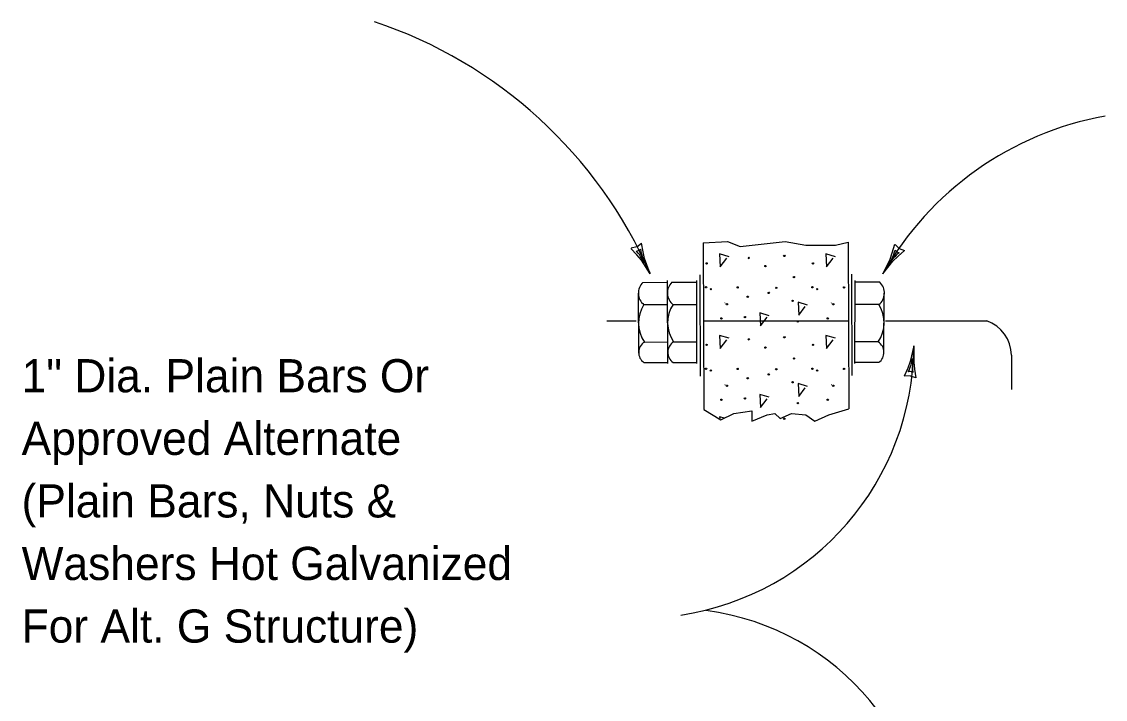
# Model space of a CAD drawing. Extents: x -7.1 to 10, y -5 to 6.
# Drawn here: x 4.345 to 6.081, y 3.626 to 4.713 of the extents above; entities that cross this region are included whole.
import ezdxf

# ---------------------------------------------------------------- set-up
doc = ezdxf.new("R2010")
doc.units = 0
for name, color, linetype in [('Level 4', 7, 'Continuous'), ('Level 5', 7, 'Continuous'), ('Level 6', 7, 'Continuous'), ('Level 7', 7, 'Continuous')]:
    doc.layers.add(name, color=color, linetype=linetype)

msp = doc.modelspace()

# ---------------------------------------------------------------- linework, layer by layer
at = {"layer": 'Level 4'}
for p, q in [((5.4372, 4.3584), (5.4383, 4.0912)), ((5.6692, 4.3594), (5.6703, 4.0921)), ((5.4327, 4.1443), (5.432, 4.307)), ((5.676, 4.1453), (5.6754, 4.308)), ((5.3403, 4.2947), (5.3794, 4.2949)), ((5.3805, 4.1646), (5.3799, 4.2976)), ((5.387, 4.2949), (5.4266, 4.2951)), ((5.4271, 4.1648), (5.4266, 4.2978)), ((5.68, 4.1648), (5.6805, 4.2978)), ((5.7201, 4.2949), (5.6805, 4.2951)), ((5.3337, 4.1812), (5.3333, 4.2776)), ((5.3804, 4.1814), (5.38, 4.2778)), ((5.7267, 4.1817), (5.7271, 4.2775)), ((5.342, 4.2591), (5.3801, 4.2593)), ((5.3887, 4.2593), (5.4268, 4.2595)), ((5.7184, 4.2593), (5.6803, 4.2595)), ((5.2826, 4.2333), (5.3295, 4.2333)), ((5.4387, 4.2333), (5.6695, 4.2333)), ((5.729, 4.2333), (5.8914, 4.2333)), ((5.3428, 4.1991), (5.3803, 4.1993)), ((5.3895, 4.1993), (5.427, 4.1995)), ((5.7176, 4.1993), (5.6801, 4.1995)), ((5.9311, 4.1782), (5.9313, 4.1233)), ((5.342, 4.1663), (5.3805, 4.1664)), ((5.3887, 4.1665), (5.4271, 4.1666)), ((5.7184, 4.1665), (5.68, 4.1666))]:
    msp.add_line(p, q, dxfattribs=at)
for points in [[(5.4372, 4.3584), (5.4758, 4.3606), (5.4964, 4.3524), (5.5685, 4.3606), (5.6015, 4.3544), (5.6489, 4.3544), (5.6692, 4.3594)], [(5.4383, 4.0912), (5.4655, 4.0742), (5.4861, 4.0845), (5.515, 4.0886), (5.515, 4.0721), (5.5397, 4.0824), (5.5521, 4.0845), (5.5603, 4.0763), (5.5788, 4.0845), (5.6015, 4.0824), (5.6159, 4.0721), (5.6386, 4.0824), (5.6703, 4.0921)]]:
    msp.add_lwpolyline(points, dxfattribs=at)
for centre, radius, start, end in [((5.3569, 4.2776), 0.0238, 134.046, 231.2659), ((5.4035, 4.2778), 0.0238, 134.046, 231.2659), ((5.7036, 4.2778), 0.0238, 308.7341, 45.954), ((5.388, 4.2298), 0.0546, 147.4718, 214.1522), ((5.4347, 4.2299), 0.0546, 147.4718, 214.1522), ((5.6724, 4.2299), 0.0546, 325.8478, 32.5281), ((5.871, 4.1767), 0.0602, 1.3903, 70.2079), ((5.3536, 4.1824), 0.0199, 122.6674, 234.2853), ((5.4003, 4.1826), 0.0199, 122.6674, 234.2853), ((5.7068, 4.1826), 0.0199, 305.7147, 57.3326)]:
    msp.add_arc(centre, radius, start, end, dxfattribs=at)
at = {"layer": 'Level 5'}
for p, q in [((5.4424, 4.3254), (5.4423, 4.3241)), ((5.5092, 4.3341), (5.5092, 4.3341)), ((5.5092, 4.3341), (5.5099, 4.3326)), ((5.5687, 4.3378), (5.5672, 4.337)), ((5.5687, 4.3378), (5.5687, 4.3378)), ((5.6127, 4.3254), (5.6127, 4.3241)), ((5.583, 4.3044), (5.5834, 4.303)), ((5.451, 4.2841), (5.451, 4.2841)), ((5.5439, 4.2804), (5.5439, 4.2804)), ((5.5538, 4.2858), (5.5538, 4.2858)), ((5.6214, 4.2841), (5.6214, 4.2841)), ((5.4719, 4.2617), (5.4721, 4.2618)), ((5.6422, 4.2617), (5.6424, 4.2618)), ((5.5904, 4.2333), (5.5904, 4.2333)), ((5.5092, 4.2036), (5.5092, 4.2036)), ((5.5092, 4.2036), (5.5099, 4.202)), ((5.5687, 4.2073), (5.5672, 4.2064)), ((5.5687, 4.2073), (5.5687, 4.2073)), ((5.4424, 4.1949), (5.4423, 4.1936)), ((5.6127, 4.1949), (5.6127, 4.1936)), ((5.583, 4.1739), (5.5834, 4.1725)), ((5.451, 4.1535), (5.451, 4.1535)), ((5.5538, 4.1553), (5.5538, 4.1553)), ((5.6214, 4.1535), (5.6214, 4.1535)), ((5.5439, 4.1498), (5.5439, 4.1498)), ((5.4719, 4.1312), (5.4721, 4.1312)), ((5.6422, 4.1312), (5.6424, 4.1312)), ((5.5904, 4.1028), (5.5904, 4.1028)), ((5.4712, 4.0769), (5.4633, 4.0794)), ((5.4633, 4.0794), (5.4635, 4.0766))]:
    msp.add_line(p, q, dxfattribs=at)
for points in [[(5.4785, 4.3358), (5.4633, 4.3405), (5.4645, 4.3195), (5.475, 4.3335)], [(5.6488, 4.3358), (5.6336, 4.3405), (5.6348, 4.3195), (5.6453, 4.3335)], [(5.6042, 4.2585), (5.589, 4.2632), (5.5902, 4.2422), (5.6007, 4.2562)], [(5.5429, 4.2412), (5.5277, 4.2458), (5.5289, 4.2249), (5.5394, 4.2388)], [(5.4785, 4.2053), (5.4633, 4.2099), (5.4645, 4.1889), (5.475, 4.2029)], [(5.6488, 4.2053), (5.6336, 4.2099), (5.6348, 4.1889), (5.6453, 4.2029)], [(5.5429, 4.1106), (5.5277, 4.1153), (5.5289, 4.0943), (5.5394, 4.1083)], [(5.6042, 4.128), (5.589, 4.1326), (5.5902, 4.1117), (5.6007, 4.1256)]]:
    msp.add_lwpolyline(points, dxfattribs=at)
for centre in [(5.4426, 4.3253), (5.5102, 4.3341), (5.5669, 4.3373), (5.6129, 4.3253), (5.5368, 4.3209), (5.5825, 4.3033), (5.4417, 4.2869), (5.4493, 4.2839), (5.4923, 4.2867), (5.5084, 4.2717), (5.5421, 4.2778), (5.5541, 4.2861), (5.6121, 4.2869), (5.6197, 4.2839), (5.6627, 4.2867), (5.4751, 4.2597), (5.5804, 4.2652), (5.6454, 4.2597), (5.4663, 4.2371), (5.504, 4.2392), (5.6366, 4.2371), (5.5887, 4.2319), (5.5102, 4.2035), (5.5669, 4.2067), (5.4426, 4.1947), (5.5368, 4.1903), (5.6129, 4.1947), (5.5825, 4.1728), (5.4417, 4.1564), (5.4493, 4.1534), (5.4923, 4.1561), (5.5541, 4.1555), (5.6121, 4.1564), (5.6197, 4.1534), (5.6627, 4.1561), (5.5084, 4.1411), (5.5421, 4.1473), (5.5804, 4.1347), (5.4751, 4.1291), (5.6454, 4.1291), (5.4663, 4.1066), (5.504, 4.1087), (5.5887, 4.1013), (5.6366, 4.1066), (5.5669, 4.0762)]:
    msp.add_circle(centre, 0.00105, dxfattribs=at)
at = {"layer": 'Level 7'}
for p, q in [((5.3307, 4.3519), (5.3218, 4.3495)), ((5.3307, 4.3519), (5.3381, 4.3576)), ((5.7511, 4.3493), (5.7444, 4.3557)), ((5.7511, 4.3493), (5.7598, 4.3459)), ((5.7685, 4.145), (5.7593, 4.1443)), ((5.7685, 4.145), (5.7773, 4.1421))]:
    msp.add_line(p, q, dxfattribs=at)
for points in [[(5.3523, 4.3084), (5.3382, 4.3303), (5.3309, 4.3389), (5.3212, 4.3492)], [(5.3431, 4.3269), (5.3395, 4.3328), (5.3368, 4.3362), (5.3348, 4.3393), (5.3328, 4.3414), (5.33, 4.3448), (5.3336, 4.3457), (5.3367, 4.3482), (5.337, 4.3444), (5.3376, 4.3418), (5.3385, 4.3391), (5.3392, 4.3365), (5.3401, 4.3342), (5.341, 4.3315), (5.3431, 4.3269)], [(5.3523, 4.3084), (5.3432, 4.3329), (5.3407, 4.3438), (5.3381, 4.3576)], [(5.7249, 4.3084), (5.7364, 4.3318), (5.74, 4.3424), (5.7439, 4.3561)], [(5.7249, 4.3084), (5.7411, 4.3288), (5.7493, 4.3366), (5.7598, 4.3459)], [(5.7359, 4.3258), (5.7391, 4.3319), (5.7407, 4.336), (5.7424, 4.3393), (5.7432, 4.3421), (5.7446, 4.3463), (5.7473, 4.3436), (5.7509, 4.3422), (5.7479, 4.3401), (5.746, 4.3382), (5.7441, 4.336), (5.7422, 4.3341), (5.7407, 4.3322), (5.7388, 4.33), (5.7359, 4.3258)], [(5.7747, 4.1931), (5.7687, 4.1678), (5.7647, 4.1573), (5.7593, 4.1443)], [(5.7747, 4.1931), (5.7743, 4.1671), (5.7756, 4.1559), (5.7779, 4.1419)], [(5.7721, 4.1727), (5.7719, 4.1658), (5.7722, 4.1614), (5.7721, 4.1578), (5.7726, 4.1549), (5.7731, 4.1505), (5.7696, 4.1518), (5.7656, 4.1514), (5.7675, 4.1547), (5.7684, 4.1572), (5.7691, 4.16), (5.7701, 4.1625), (5.7706, 4.1649), (5.7713, 4.1677), (5.7721, 4.1727)]]:
    msp.add_lwpolyline(points, dxfattribs=at)
for centre, radius, start, end in [((4.6753, 4.012), 0.7391, 23.645, 71.4722), ((6.1727, 4.055), 0.5146, 100.2192, 150.4935), ((5.336, 4.1952), 0.4386, 278.5606, 359.7353), ((5.3888, 3.3617), 0.4103, 357.0056, 82.5558)]:
    msp.add_arc(centre, radius, start, end, dxfattribs=at)

# ---------------------------------------------------------------- texts
at = {"layer": 'Level 6'}
for s, p in [('1" Dia. Plain Bars Or', (4.3449, 4.1186)), ('Approved Alternate', (4.3449, 4.0182)), ('(Plain Bars, Nuts &', (4.3449, 3.9179)), ('Washers Hot Galvanized', (4.3449, 3.8176)), ('For Alt. G Structure)', (4.3449, 3.7172))]:
    msp.add_text(s, height=0.053135, dxfattribs=at).set_placement(p)

doc.saveas('drawing.dxf')
